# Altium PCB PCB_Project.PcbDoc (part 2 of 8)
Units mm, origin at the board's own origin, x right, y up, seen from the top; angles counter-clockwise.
Board outline 250 x 200 mm, 6 copper layers (Top Shielding/Sig, Sig 1, PWR, GND, Sig 4, Bottom Shielding/Sig), stack 1.568 mm thick; 736 components, 420 nets, 1929 pads, 2185 vias.
Unrouted connection lines stored in the file: 47.
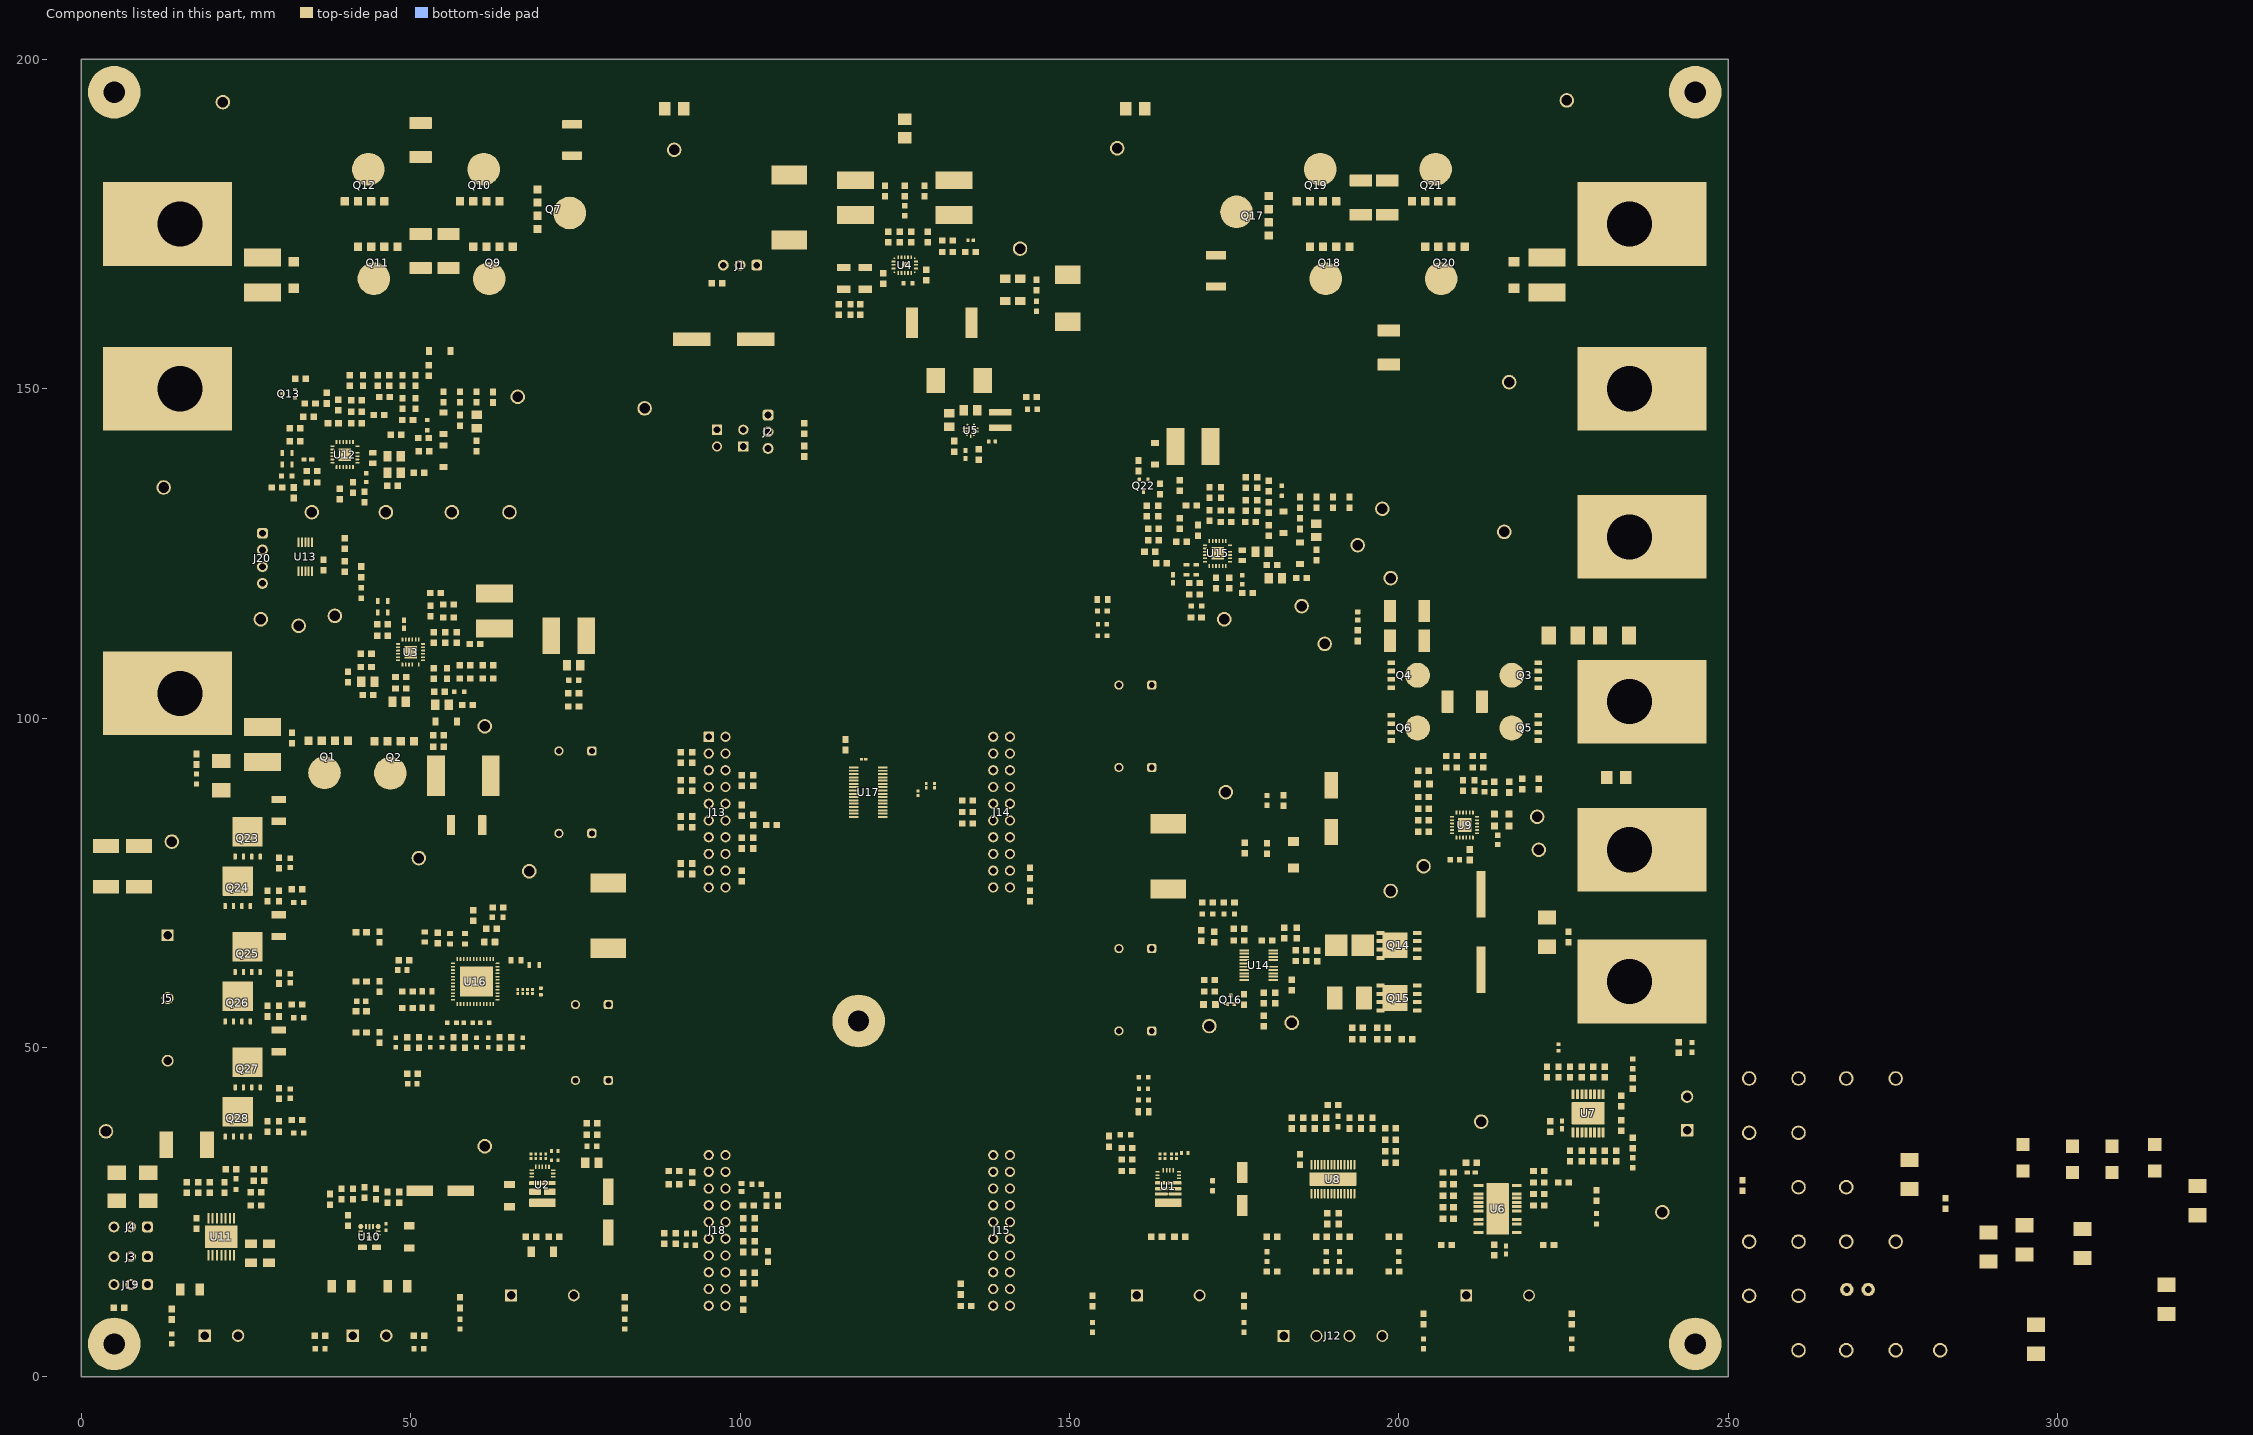
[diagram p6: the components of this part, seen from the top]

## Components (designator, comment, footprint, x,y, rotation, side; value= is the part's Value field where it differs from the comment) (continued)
R215 "RC0603FR-07205RL" 0603 174.25,72 r180 top value=205
R216 "VMP-1R00-1.0-U" FP-VMP-1R00-1.0-U_2010-MFG 172.25,167.875 r90 top value=1
R217 "CRCW06030000Z0EA" 0603 163.75,134.75 r90 top value=0
R218 "CRCW06030000Z0EA" 0603 161.75,131.45 r90 top value=0
R219 "CRCW06030000Z0EA" 0603 180.75,123.25 r0 top value=0
R220 "CSS2H-2512R-L500F" FP-CSS2H-2512R-L500F_2512-MFG 194.25,179 r90 top value=500µ
R221 "RC0805FR-0710RL" 0805_HV 181.25,121.25 r180 top value=10.0
R222 "CSS2H-2512R-L500F" FP-CSS2H-2512R-L500F_2512-MFG 198.25,179 r90 top value=500µ
R223 "HoLRS2512-0.25mR-1%" FP-HoLRS2512_2512-MFG 198.5,156.25 r90 top value=250µ
R224 "CRCW06030000Z0EA" 0603 176.75,135.75 r90 top value=0
R225 "CRCW06030000Z0EA" 0603 178.5,135.75 r90 top value=0
R226 "CRCW06030000Z0EA" 0603 168.5,132.25 r180 top value=0
R227 "ERJ-3EKF1000V" 0603 173,134.25 r90 top value=100
R228 "RC0603FR-07200RL" 0603 176.75,132.25 r90 top value=200
R229 "RC0603FR-07200RL" 0603 178.5,132.25 r90 top value=200
R230 "RC0603FR-072R21L" 0603 187.5,132.75 r90 top value=2.21
R231 "RC0603FR-072R21L" 0603 192.5,132.75 r90 top value=2.21
R232 "RC0603FR-072R21L" 0603 190,132.75 r90 top value=2.21
R233 "RC0603FR-072R21L" 0603 185,132.75 r90 top value=2.21
R234 "RC0805FR-0710RL" 0805_HV 187.5,128.5 r90 top value=10.0
R235 "RC0603FR-07300KL" 0603 167,126.75 r180 top value=300k
R236 "RC0603FR-0775KL" 0603 160.5,138.3 r90 top value=75.0k
R237 "RC0603FR-071KL" 0603 162.75,127 r0 top value=1.00k
R238 "RC0603FR-07698RL" 0603 171.25,134.25 r90 top value=698
R239 "RC0603FR-071KL" 0603 162.75,128.75 r0 top value=1.00k
R240 "CRCW06030000Z0EA" 0603 180.25,131.95 r270 top value=0
R241 "RC0603FR-07309RL" 0603 180.25,135.2 r90 top value=309
R242 "RC0603FR-071KL" 0603 162.2,125.25 r0 top value=1.00k
R243 "CRCW06030000Z0EA" 0603 185,129.5 r270 top value=0
R244 "RC0603FR-07205RL" 0603 169.25,115.25 r180 top value=205
R245 "TNPW060310K0BEEA" TNPW0603 169.25,122.5 r270 top value=10.0k
R246 "RC0603FR-071KL" 0603 144,76.5 r90 top value=1.00k
R247 "TNPW060310K0BEEA" TNPW0603 167.75,122.5 r270 top value=10.0k
R248 "RC0603FR-071KL" 0603 144,73 r90 top value=1.00k
R249 "RC0603FR-072K2L" 0603 92.75,84.25 r90 top value=2.20k
R250 "RC0603FR-0712K1L" 0603 174.25,120.5 r90 top value=12.1k
R251 "CRCW0603100KFKEA" 0603 169,118.75 r0 top value=100k
R252 "RC0603FR-0740K2L" 0603 172.25,120.5 r90 top value=40.2k
R253 "RC0603FR-072K49L" 0603 32.75,74 r180 top value=2.49k
R254 "RC0603FR-072K49L" 0603 32.75,56.5 r180 top value=2.49k
R255 "RC0603FR-072K49L" 0603 32.75,39 r180 top value=2.49k
R256 "RC0201FR-0722RL" 0201 67.75,58.5 r90 top value=22.0
R257 "RC0402JR-0710KL" FP-RC0402JR-0710KL_0402-MFG 69.75,58.5 r270 top value=10k
R258 "RC0201FR-0722RL" 0201 67,58.5 r90 top value=22.0
R259 "RC0201FR-0722RL" 0201 66.25,58.5 r90 top value=22.0
R260 "RC0201FR-0722RL" 0201 68.5,58.5 r90 top value=22.0
R261 "CRCW0603100KFKEA" 0603L 31.75,78 r270 top value=100k
R262 "TNPW060310K0BEEA" TNPW0603 68.75,62.5 r0 top value=10.0k
R263 "KTR03EZPF3R00" 0603 54.125,66.625 r90 top value=3.00
R264 "ERJ-3GEY0R00V" 0603 45.25,66.75 r270 top value=0
R265 "CRCW0603100KFKEA" 0603L 48.75,61.75 r0 top value=100k
R266 "CRCW0603100KFKEA" 0603L 31.75,60.5 r270 top value=100k
R267 "RC0603FR-07205RL" 0603 63.25,71.25 r0 top value=205
R268 "ERJ-3GEY0R00V" 0603 49,63.25 r0 top value=0
R269 "KTR03EZPF3R00" 0603 49.5,58.5 r0 top value=3.00
R270 "CRCW0603100KFKEA" 0603L 42.5,57 r0 top value=100k
R271 "ERJ-3GEY0R00V" 0603 45.25,59.25 r270 top value=0
R272 "ERJ-3GEY0R00V" 0603 42.5,55.5 r0 top value=0
R273 "CRCW0603100KFKEA" 0603L 31.75,43 r270 top value=100k
R274 "KTR03EZPF3R00" 0603 49.5,56 r0 top value=3.00
R275 "ERJ-3GEY0R00V" 0603 45.25,51.5 r270 top value=0
R276 "ERJ-3GEY0R00V" 0603 50.25,46 r0 top value=0
R277 "CRCW0603100KFKEA" 0603L 50.25,44.5 r0 top value=100k
R278 "RC0603FR-07160RL" 0603 91,89.75 r270 top value=160
R279 "RC0603FR-07160RL" 0603 91,77.125 r270 top value=160
R280 "RC0603FR-07160RL" 0603 104.75,83.75 r0 top value=160
R281 "RC0603FR-0710RL" 0603 49.5,50.75 r270 top value=10.0
R282 "RC0603FR-0710RL" 0603 56.5,50.75 r270 top value=10.0
R283 "RC0603FR-0710RL" 0603 63.5,50.75 r270 top value=10.0
R284 "CRE2512-FZ-R005E-3" CRE2512-R5_R9 8.75,77.5 r270 top value=0.005
R285 "CRE2512-FZ-R005E-3" CRE2512-R5_R9 3.75,77.5 r270 top value=0.005
R286 "CRE2512-FZ-R005E-3" CRE2512-R5_R9 16,35.25 r0 top value=0.005
R287 "RC0603FR-0710RL" 0603 51.25,50.75 r270 top value=10.0
R288 "RC0603FR-0710RL" 0603 58.25,50.75 r270 top value=10.0
R289 "RC0603FR-0710RL" 0603 65.25,50.75 r270 top value=10.0
R290 "ERJ-3EKF1002V" 0603 134.5,87.5 r180 top value=10.0k
R291 "ERJ-3EKF1002V" 0603 134.5,84 r180 top value=10.0k
R292 "ERJ-3EKF1002V" 0603 134.5,85.75 r180 top value=10.0k
R293 "RC0201FR-0722RL" 0201 128.25,89.75 r90 top value=22.0
R294 "RC0201FR-0722RL" 0201 129.5,89.75 r90 top value=22.0
R295 "RC0201FR-0722RL" 0201 118.75,93.75 r180 top value=22.0
R296 "RC0201FR-0722RL" 0201 127,88.58 r90 top value=22.0
R297 "RC0603FR-073K16L" 0603 164,123.5 r0 top value=3.16k
R298 "RC0603FR-07102RL" 0603 52.75,152.75 r90 top value=102
R299 "RC0603FR-0733KL" 0603 39.25,134 r90 top value=33.0k
R300 "RC0603FR-0710RL" 0603 180.25,128.45 r90 top value=10.0
R301 "RC0603FR-07102RL" 0603 166.75,135.3 r90 top value=102
R302 "RC0603FR-071KL" 0603 40,126.5 r90 top value=1.00k
R303 "RC0603FR-0715K4L" 0603 40,123 r90 top value=15.4k
R304 "RNCF0603TKY10K0" 0603 5.7,10.5 r180 top value=10.0k
R305 "CRCW06030000Z0EA" 0603 46,148.75 r180 top value=0
R306 "RC0603FR-0710RL" 0603 283,26.3 r90 top value=10.0
R307 "RC0603FR-0710RL" 0603 252.173,29.036 r90 top value=10.0
RNTC_1 "NCU18WB473J6SRB" FP-NCU18WB473J6SRB_0603-MFG 57.375,104 r0 top value=47kΩ
RNTC_2 "NCU18WB473J6SRB" FP-NCU18WB473J6SRB_0603-MFG 52.5,144.475 r90 top value=47kΩ
RNTC_3 "NCU18WB473J6SRB" FP-NCU18WB473J6SRB_0603-MFG 182.25,134.5 r90 top value=47kΩ
S1 "LPM Button" SW_147873-2 7.75,31 r0 top
S2 "RST" SW_147873-2 7.75,26.75 r180 top
SH-J1 "SNT-100-BK-G" SNT-100-BK-G 100,168.75 r180 top value=1x2
SH-J2 "SNT-100-BK-G" SNT-100-BK-G 104.75,142.5 r90 top value=1x2
SH-J3 "SNT-100-BK-G" SNT-100-BK-G 96.5,142.5 r90 top value=1x2
SH-J4 "SNT-100-BK-G" SNT-100-BK-G 100.5,142.5 r90 top value=1x2
T1 "JUMP_START" Panduit_CXS70-14-C 235,80 r180 top locked
T2 "12V_OFF_BOARD_DCDC" Panduit_CXS70-14-C 235,102.5 r180 top locked
T3 "48V_OFF_BOARD_DCDC" Panduit_CXS70-14-C 235,127.5 r180 top locked
T4 "48V_BAT_IN1" Panduit_CXS70-14-C 15,175 r0 top locked
T5 "GND" Panduit_CXS70-14-C 15,150 r0 top locked
T6 "48V_BAT_IN2" Panduit_CXS70-14-C 235,175 r180 top
T7 "GND" Panduit_CXS70-14-C 235,150 r180 top locked
T8 "VOUT_TPS1214" Panduit_CXS70-14-C 15,103.75 r0 top locked
T9 "VOUT_TPS1211" Panduit_CXS70-14-C 235,60 r180 top locked
TP1 "12V_DRV8245" Keystone5010 171.25,53.25 r180 top
TP2 "48V" Keystone5010 51.25,78.75 r180 top
TP3 "48V_DRV8263" Keystone5010 61.25,35 r90 top
TP4 "G_TPS1214" Keystone5012 27.25,115 r180 top
TP5 "GATE_TPS1214" Keystone5012 61.25,98.75 r180 top
TP6 "I2t_TPS1214" Keystone5012 33,114 r0 top
TP7 "IMON_TPS1214" Keystone5012 38.5,115.5 r0 top
TP8 "COBRA_VOUT" Keystone5010 142.5,171.25 r180 top
TP9 "12V_IN" Keystone5010 221.25,80 r90 top
TP10 "12V" Keystone5010 198.75,121.25 r90 top
TP11 "HGATE_LM74900" Keystone5012 188.75,111.25 r0 top
TP12 "DGATE_LM74900" Keystone5012 221,85 r90 top
TP13 "G_TPS1212_input1" Keystone5012 56.25,131.25 r90 top
TP14 "48V" Keystone5010 85.5,147 r90 top
TP15 "48V_BAT_IN1" Keystone5010 21.5,193.5 r90 top
TP16 "GATE_TPS1212_input1" Keystone5012 66.25,148.75 r0 top
TP17 "I2t_TPS1212_input1" Keystone5012 46.25,131.25 r90 top
TP18 "IMON_TPS1212_input1" Keystone5012 35,131.25 r0 top
TP19 "G_TPS1211" Keystone5012 183.75,53.75 r90 top
TP20 "TPS1211_VS" Keystone5010 212.5,38.75 r180 top
TP21 "GATE_TPS1211" Keystone5012 198.75,73.75 r0 top
TP22 "IMON_TPS1211" Keystone5012 173.75,88.75 r0 top
TP23 "G_TPS1212_input2" Keystone5012 185.25,117 r90 top
TP24 "48V" Keystone5010 216,128.25 r90 top
TP25 "48V_BAT_IN2" Keystone5010 225.5,193.75 r90 top
TP26 "GATE_TPS1212_input2" Keystone5012 197.5,131.75 r90 top
TP27 "I2t_TPS1212_input2" Keystone5012 193.75,126.25 r0 top
TP28 "IMON_TPS1212_input2" Keystone5012 173.5,115 r0 top
TP29 "GND" Keystone5011 65,131.25 r0 top
TP30 "GND" Keystone5011 13.75,81.25 r180 top
TP31 "GND" Keystone5011 12.5,135 r180 top
TP32 "GND" Keystone5011 157.25,186.5 r0 top
TP33 "GND" Keystone5011 68,76.75 r0 top
TP34 "GND" Keystone5011 90,186.25 r0 top
TP35 "GND" Keystone5011 203.75,77.5 r90 top
TP36 "GND" Keystone5011 240,25 r0 top
TP37 "GND" Keystone5011 3.75,37.25 r90 top
TP38 "GND" Keystone5011 216.75,151 r0 top
TP39 "VS+" Keystone5012 275.423,45.286 r0 top
TP40 "VS-" Keystone5012 267.923,45.286 r0 top
TP41 "VDD+" Keystone5012 275.423,4.036 r0 top
TP42 "VDD-" Keystone5012 282.173,4.036 r0 top
TP43 "VBB+" Keystone5012 260.673,4.036 r0 top
TP44 "VBB-" Keystone5012 267.923,4.036 r0 top
TP45 "VBB+" Keystone5012 260.673,28.786 r0 top
TP46 "VBB-" Keystone5012 267.923,28.786 r0 top
TP47 "5002" Keystone5002 271.25,13.25 r90 top
TP48 "5002" Keystone5002 268,13.25 r90 top
TP49 "VS+" Keystone5012 275.423,20.536 r0 top
TP50 "VS-" Keystone5012 267.923,20.536 r0 top
TP51 "1212_1_SRC" Keystone5012 260.673,12.286 r0 top
TP52 "1212_1_BST" Keystone5012 253.173,12.286 r0 top
TP53 "1212_2_SRC" Keystone5012 260.673,20.536 r0 top
TP54 "1212_2_BST" Keystone5012 253.173,20.536 r0 top
TP55 "1214_SRC" Keystone5012 260.673,45.286 r0 top
TP56 "1214_BST" Keystone5012 253.173,45.286 r0 top
TP57 "1211_SRC" Keystone5012 260.673,37.036 r0 top
TP58 "1211_BST" Keystone5012 253.173,37.036 r0 top
U1 "DRV8245SQRXZRQ1" RXZ0016A-MFG 165,28.75 r0 top
U2 "DRV8263SQVAKRQ1" VAK0015A-MFG 70,29 r0 top locked
U3 "TPS12140-Q1" RGE0023A-MFG#1 50,110 r270 top
U4 "LM68645SCRZTRQ1" RZT0020A-MFG 125,168.75 r270 top locked
U5 "TPS62903QRYTQ1" RYT0009A-MFG 135,143.75 r180 top locked
U6 "TPS2HCS05A" PWC0018A-MFG 215,25.5 r0 top locked
U7 "TPS2HCS10-Q1" PWP0016P-MFG 228.75,40 r90 top
U8 "TPS4HC120-Q1" DGQ0028A-MFG 190,30 r270 top locked
U9 "LM74900QRGERQ1" RGE0024T-MFG 210,83.75 r180 top locked
U10 "TPS482H85BQCHURQ1" CHU0012A-MFG 43.75,21.25 r90 top locked
U11 "TPS1HTC30AQPWPRQ1" PWP0014C-MFG 21.25,21.25 r270 top locked
U12 "TPS12120-Q1" RGE0023A-MFG#2 40,140 r0 top
U13 "TPLD1201DGS" DGS0010A-MFG 34,124.5 r270 top
U14 "TPS12111LQDGXRQ1" DGX0019A-MFG 178.75,62.5 r0 top locked
U15 "TPS12120-Q1" RGE0023A-MFG#2 172.5,125 r0 top
U16 "DRV8363RGZRQ1" RGZ0048L-MFG 59.812,60 r90 top locked
U17 "TXE8124QDGSRQ1" DGS0032A-MFG 119.45,88.75 r0 top
ZZ1 "This Assembly Note is for PCB labels only" AssemblyNoteLabel 201,-3 r0 top
ZZ2 "These assemblies are ESD sensitive, ESD precautions shall be observed." AssemblyNote 201,-5 r0 top
ZZ3 "These assemblies must be clean and free from flux and all contaminants. Use of no clean flux is not acceptable." AssemblyNote 201,-7 r0 top
ZZ4 "These assemblies must comply with workmanship standards IPC-A-610 Class 2, unless otherwise specified." AssemblyNote 201,-9 r0 top

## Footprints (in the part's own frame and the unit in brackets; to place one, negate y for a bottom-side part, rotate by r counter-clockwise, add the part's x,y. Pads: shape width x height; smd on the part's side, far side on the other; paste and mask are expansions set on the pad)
0201 [mm] "Data from Kemet datasheet CC101_COM dated 7/28/11"
  rect 0.46x0.42 smd mask+0.048: 1(-0.33,0) 2(0.33,0)
  body extent -0.31,-0.16 0.31,0.16, height 0.26
0402 [mm] "0402 from SM-752 data"
  rect 0.8x0.6 smd: 1(-0.6,0) 2(0.6,0)
  silkscreen extent -1.22,-0.52 1.22,0.52, body extent -0.55,-0.3 0.55,0.3, height 0.6
0603 [mm] "0603 from SM-752 data"
  rect 1x0.95 smd: 1(-0.8,0) 2(0.8,0)
  silkscreen extent -1.52,-0.69 1.52,0.69, body extent -0.87,-0.47 0.87,0.47, height 1
0603L [mm] "0603 from SM-752 data"
  rect 0.8x0.85 smd: 1(-0.7,0) 2(0.7,0)
  silkscreen extent -0.07,-0.33 0.07,0.32, body extent -0.87,-0.47 0.87,0.47, height 1
0805_HV [mil] "0805 with 30mil clearance between pads"
  rect 50x63 smd: 1(-40,0) 2(40,0)
  silkscreen extent -74,-40 74,40, body extent -43,-29 43,29, height 57
1206 [mm] "1206 from SM-752 data"
  rect 1.3x1.85 smd: 1(-1.45,0) 2(1.45,0)
  silkscreen extent -2.4,-1.21 2.4,1.21, body extent -1.7,-0.9 1.7,0.9, height 1.35
1206_180 [mm] "1206_180"
  rect 1.1x1.6 smd: 1(-1.7,0) 2(1.7,0)
  silkscreen extent -0.9,-1 0.9,1, body extent -1.75,-0.95 1.75,0.95, height 1.8
1210_280 [mm] "SMD, 2-Leads, Body 3.6x2.8mm, Height 2.8mm"
  rect 1.1x2.2 smd: 1(-1.65,0) 2(1.65,0)
  silkscreen extent -0.84,-1.4 0.84,1.4, body extent -1.8,-1.4 1.8,1.4, height 2.8
AFK_1250x1350 [mm] "SMD, 2-Leads, Dia 12.5mm"
  rect 7.05x1.35 smd: 1(-5.725,0) 2(5.725,0)
  silkscreen extent -6.75,-6.75 6.75,6.75, body extent -7.5,-6.75 7.5,6.75, height 14
AssemblyNote [mm] "Assembly Note"
AssemblyNoteLabel [mm] "Assembly Note for PCB Labels"
BoosterPack_40pin_J1J3 [mm] "Receptacle, 2.54mm, 10x2, TH"
  rrect6% 1.55x1.55 hole 1.02: 1(1.27,11.43)
  round 1.55 hole 1.02: 2(1.27,8.89) 3(1.27,6.35) 4(1.27,3.81) 5(1.27,1.27) 6(1.27,-1.27) 7(1.27,-3.81) 8(1.27,-6.35) 9(1.27,-8.89) 10(1.27,-11.43) 21(-1.27,11.43) 22(-1.27,8.89) 23(-1.27,6.35) 24(-1.27,3.81) 25(-1.27,1.27) 26(-1.27,-1.27) 27(-1.27,-3.81) 28(-1.27,-6.35) 29(-1.27,-8.89) 30(-1.27,-11.43)
  silkscreen extent -7.62,-12.95 7.62,12.95, body extent -2.48,-12.95 2.48,12.95, height 8.51
BoosterPack_40pin_J2J4 [mm] "Receptacle, 2.54mm, 10x2, TH"
  round 1.55 hole 1.02: 11(-1.27,-11.43) 12(-1.27,-8.89) 13(-1.27,-6.35) 14(-1.27,-3.81) 15(-1.27,-1.27) 16(-1.27,1.27) 17(-1.27,3.81) 18(-1.27,6.35) 19(-1.27,8.89) 20(-1.27,11.43) 31(1.27,-11.43) 32(1.27,-8.89) 33(1.27,-6.35) 34(1.27,-3.81) 35(1.27,-1.27) 36(1.27,1.27) 37(1.27,3.81) 38(1.27,6.35) 39(1.27,8.89) 40(1.27,11.43)
  silkscreen extent -7.62,-12.95 2.48,12.95, body extent -2.48,-12.95 2.48,12.95, height 8.51
BoosterPack_40pin_J5J7 [mm] "Receptacle, 2.54mm, 10x2, TH"
  round 1.55 hole 1.02: 41(1.27,11.43) 42(1.27,8.89) 43(1.27,6.35) 44(1.27,3.81) 45(1.27,1.27) 46(1.27,-1.27) 47(1.27,-3.81) 48(1.27,-6.35) 49(1.27,-8.89) 50(1.27,-11.43) 61(-1.27,11.43) 62(-1.27,8.89) 63(-1.27,6.35) 64(-1.27,3.81) 65(-1.27,1.27) 66(-1.27,-1.27) 67(-1.27,-3.81) 68(-1.27,-6.35) 69(-1.27,-8.89) 70(-1.27,-11.43)
  silkscreen extent -7.62,-12.95 7.62,12.95, body extent -2.48,-12.95 2.48,12.95, height 8.51
BoosterPack_40pin_J6J8 [mm] "Receptacle, 2.54mm, 10x2, TH"
  round 1.55 hole 1.02: 51(-1.27,-11.43) 52(-1.27,-8.89) 53(-1.27,-6.35) 54(-1.27,-3.81) 55(-1.27,-1.27) 56(-1.27,1.27) 57(-1.27,3.81) 58(-1.27,6.35) 59(-1.27,8.89) 60(-1.27,11.43) 71(1.27,-11.43) 72(1.27,-8.89) 73(1.27,-6.35) 74(1.27,-3.81) 75(1.27,-1.27) 76(1.27,1.27) 77(1.27,3.81) 78(1.27,6.35) 79(1.27,8.89) 80(1.27,11.43)
  silkscreen extent -7.62,-12.95 2.48,12.95, body extent -2.48,-12.95 2.48,12.95, height 8.51
CE_Mark_5mm [mm] "Minimum text height for CE Mark"
  silkscreen extent -3.5,-2.5 3.5,2.5
CHU0012A-MFG [mm]
  rrect25% 0.8x1.4 smd paste-1000 mask-1000: 1(-1.6,1.05) 2(-1.6,-1.05)
  round 0.691 smd paste-1000 mask+0: 3(-0.162,0.042)
  rrect40% 0.25x0.7 smd paste+0 mask+0: 4(0.325,-1.35) 5(0.825,-1.35) 11(0.825,1.35) 12(0.325,1.35)
  round 0.764 smd paste-1000 mask-1000: 6(1.575,-1.325) 10(1.575,1.326)
  rrect33% 0.75x0.3 smd paste+0 mask+0: 7(1.575,-0.55) 9(1.575,0.55)
  rrect33% 0.8x0.3 smd paste+0 mask+0: 8(1.55,0)
  Top Shielding/Sig region: 1.25,-1.75 1.212,-1.742 1.179,-1.721 1.158,-1.688 1.15,-1.65 1.15,-1.65 1.15,-1.116 1.166,-1.034 1.213,-0.964 1.283,-0.917 1.365,-0.901 1.365,-0.901 1.9,-0.901 1.95,-0.914 1.987,-0.951 2,-1.001 2,-1.001 2,-1.65 1.987,-1.7 1.95,-1.737 1.9,-1.75 1.9,-1.75
  Top Shielding/Sig region: 1.25,1.75 1.212,1.742 1.179,1.721 1.158,1.688 1.15,1.65 1.15,1.65 1.15,1.116 1.166,1.034 1.213,0.964 1.283,0.917 1.365,0.901 1.365,0.901 1.9,0.901 1.938,0.909 1.971,0.93 1.992,0.963 2,1.001 2,1.001 2,1.65 1.992,1.688 1.971,1.721 1.938,1.742 1.9,1.75 1.9,1.75
  Top Shielding/Sig region: -0.65,1.65 -0.643,1.675 -0.625,1.693 -0.6,1.7 -0.6,1.7 -0.45,1.7 -0.431,1.696 -0.415,1.685 -0.404,1.669 -0.4,1.65 -0.4,1.65 -0.4,0.863 -0.392,0.825 -0.371,0.793 -0.371,0.793 0.093,0.329 0.125,0.308 0.163,0.3 0.163,0.3 0.415,0.3 0.44,0.293 0.458,0.275 0.465,0.25 0.465,0.25 0.465,-0.25 0.458,-0.275 0.44,-0.293 0.415,-0.3 0.415,-0.3 0.163,-0.3 0.125,-0.308 0.093,-0.329 0.093,-0.329 -0.371,-0.8 -0.392,-0.832 -0.4,-0.87 -0.4,-0.87 -0.4,-1.65 -0.404,-1.669 -0.415,-1.685 -0.431,-1.696 -0.45,-1.7 -0.45,-1.7 -0.6,-1.7 -0.625,-1.693 -0.643,-1.675 -0.65,-1.65 -0.65,-1.65
  silkscreen extent -2.62,-1.92 2.18,1.93, body extent -2.1,-1.85 2.1,1.85, height 0.25
CRE2512-R5_R9 [mm] "SMD, 2-Leads, Body 6.45x3.35mm, Pitch 6.2mm"
  rect 2.1x4 smd: 1(-3.1,0) 2(3.1,0)
  silkscreen extent -1.6,-1.78 1.6,1.78, body extent -3.32,-1.77 3.32,1.77, height 0.9
DGQ0028A-MFG [mm]
  rrect33% 1.4x0.3 smd paste+0 mask+0: 1(-2.2,3.25) 2(-2.2,2.75) 3(-2.2,2.25) 4(-2.2,1.75) 5(-2.2,1.25) 6(-2.2,0.75) 7(-2.2,0.25) 8(-2.2,-0.25) 9(-2.2,-0.75) 10(-2.2,-1.25) 11(-2.2,-1.75) 12(-2.2,-2.25) 13(-2.2,-2.75) 14(-2.2,-3.25) 15(2.2,-3.25) 16(2.2,-2.75) 17(2.2,-2.25) 18(2.2,-1.75) 19(2.2,-1.25) 20(2.2,-0.75) 21(2.2,-0.25) 22(2.2,0.25) 23(2.2,0.75) 24(2.2,1.25) 25(2.2,1.75) 26(2.2,2.25) 27(2.2,2.75) 28(2.2,3.25)
  rrect5% 2x7.1 smd paste-1000 mask-1000: 29(0,0)
  silkscreen extent -3.57,-3.93 1.55,3.93, body extent -2.46,-3.55 2.46,3.55, height 1.1
DGS0010A-MFG [mm]
  rrect33% 1.45x0.3 smd paste+0 mask+0: 1(-2.2,1) 2(-2.2,0.5) 3(-2.2,0) 4(-2.2,-0.5) 5(-2.2,-1) 6(2.2,-1) 7(2.2,-0.5) 8(2.2,0) 9(2.2,0.5) 10(2.2,1)
  silkscreen extent -3.6,-1.55 1.05,1.55, body extent -3.03,-1.8 3.03,1.8, height 0.25
DGS0032A-MFG [mm]
  rrect33% 1.45x0.3 smd paste+0 mask+0: 1(-2.2,3.75) 2(-2.2,3.25) 3(-2.2,2.75) 4(-2.2,2.25) 5(-2.2,1.75) 6(-2.2,1.25) 7(-2.2,0.75) 8(-2.2,0.25) 9(-2.2,-0.25) 10(-2.2,-0.75) 11(-2.2,-1.25) 12(-2.2,-1.75) 13(-2.2,-2.25) 14(-2.2,-2.75) 15(-2.2,-3.25) 16(-2.2,-3.75) 17(2.2,-3.75) 18(2.2,-3.25) 19(2.2,-2.75) 20(2.2,-2.25) 21(2.2,-1.75) 22(2.2,-1.25) 23(2.2,-0.75) 24(2.2,-0.25) 25(2.2,0.25) 26(2.2,0.75) 27(2.2,1.25) 28(2.2,1.75) 29(2.2,2.25) 30(2.2,2.75) 31(2.2,3.25) 32(2.2,3.75)
  silkscreen extent -2.32,-4.1 1,4.57, body extent -3.03,-4.35 3.03,4.35, height 0.25
DGX0019A-MFG [mm] "Recommended Land Pattern"
  rrect33% 1.45x0.3 smd paste+0 mask+0: 1(-2.2,2.25) 2(-2.2,1.75) 3(-2.2,1.25) 4(-2.2,0.75) 5(-2.2,0.25) 6(-2.2,-0.25) 7(-2.2,-0.75) 8(-2.2,-1.25) 9(-2.2,-1.75) 10(-2.2,-2.25) 11(2.2,-2.25) 12(2.2,-1.75) 13(2.2,-1.25) 14(2.2,-0.75) 15(2.2,-0.25) 17(2.2,0.75) 18(2.2,1.25) 19(2.2,1.75) 20(2.2,2.25)
  silkscreen extent -3.6,-2.6 1.1,2.6, body extent -3.03,-2.85 3.03,2.85, height 0.25
Diode_1408 [mm] "On Semi recommended land pattern for SOD-123"
  rect 1.75x2 smd: 1(-1.425,0) 2(1.425,0)
  silkscreen extent -2.97,-1.35 2.26,1.35, body extent -1.8,-1.05 1.8,1.05, height 1.35
DQJ0008A [mm] "SMD, 8-Leads, Body 5.75x4.9mm"
  rrect39% 0.91x0.51 smd paste-0.05 mask-0.05: 1(-2.795,1.905) 2(-2.795,0.635) 3(-2.795,-0.635) 4(-2.795,-1.905) 5(2.795,-1.905) 6(2.795,-0.635) 7(2.795,0.635) 8(2.795,1.905)
  rrect8% 1.58x1.25 on Top Paste: 9(-0.38,1.45) 9(-0.38,0) 9(-0.38,-1.45) 9(1.4,-1.45) 9(1.4,0) 9(1.4,1.45)
  rrect3% 3.48x4.47 on Top Solder: 9(0.55,0)
  rrect2% 4.49x4.57 smd paste-2.5 mask-2.5: 9(1.005,0)
  silkscreen extent -3,-2.6 3,2.6, body extent -3.13,-2.45 3.13,2.45, height 1.15
FCC_disclaimer [mm]
Foxconn_HB3902U [mm] "Header, 2.54mm, 2x1, TH"
  rrect6% 1.55x1.55 hole 1.02: 1(-1.27,0)
  round 1.55 hole 1.02: 2(1.27,0)
  silkscreen extent -2.42,-1.7 2.41,1.23, body extent -2.41,-1.23 2.42,1.24, height 8.38
FP-06035C104J4Z2A_0603-MFG [mm]
  rrect13% 0.8x0.75 smd paste+0 mask+0: 1(-0.75,0) 2(0.75,0)
  silkscreen extent -0.87,-0.77 0.87,0.77, body extent -1.25,-0.58 1.25,0.58, height 0.25
FP-885012206120_0603-MFG [mm]
  rrect13% 0.8x0.8 smd paste+0 mask+0: 1(-0.75,0) 2(0.75,0)
  silkscreen extent -0.85,-0.78 0.85,0.77, body extent -1.25,-0.55 1.25,0.55, height 0.25
FP-AGC0603X7R250-105KXP_0603-MFG [mm] "Recommended Land Pattern"
  rrect10% 1x1 smd paste+0 mask+0: 1(-0.8,0) 2(0.8,0)
  silkscreen extent -0.87,-0.87 0.87,0.87, body extent -1.4,-0.6 1.4,0.6, height 0.25
FP-ALN2512F50R0E-1_2512-MFG [mm]
  rrect3% 3.4x3.3 smd paste+0 mask+0: 1(-2.005,0) 2(2.005,0)
  silkscreen extent -3.25,-2.09 3.24,2.07, body extent -3.8,-1.75 3.8,1.75, height 0.25
FP-BUK7J1R4-40HX_LFPAK56E-MFG [mm]
  rrect14% 0.7x1.15 smd paste-1000 mask+0: 1(-1.905,-3.137) 2(-0.635,-3.137) 3(0.635,-3.137) 4(1.905,-3.137)
  round 3.78 smd paste-1000 mask+0: 5(0,0.845)
  Top Shielding/Sig region: -2.35,3.087 2.35,3.087 2.35,1.588 2.1,1.588 2.1,-1.512 -2.1,-1.512 -2.1,1.587 -2.35,1.587
  silkscreen extent -2.65,-4.43 2.65,-1.89, body extent -2.9,-3.81 2.9,3.19, height 0.25
FP-C0402C100K5RAC7867_0402-MFG [mm]
  rrect19% 0.52x0.52 smd paste+0 mask+0: 1(-0.4,0) 2(0.4,0)
  silkscreen extent -0.5,-0.63 0.5,0.64, body extent -0.8,-0.4 0.8,0.4, height 0.25
FP-C0603C104J5RAC7867_0603-MFG [mm]
  rrect13% 0.75x0.9 smd paste+0 mask+0: 1(-0.6,0) 2(0.6,0)
  silkscreen extent -0.87,-0.83 0.88,0.82, body extent -1.2,-0.6 1.2,0.6, height 0.25
FP-CGA3E2X7R1H102K080AA_0603-MFG [mm]
  rrect14% 0.7x0.7 smd paste+0 mask+0: 1(-0.7,0) 2(0.7,0)
  silkscreen extent -0.95,-0.72 0.95,0.72, body extent -1.15,-0.65 1.15,0.65, height 0.25
FP-CL10B104KA8VPJC_0603-MFG [mm]
  rrect13% 0.79x1 smd paste+0 mask+0: 1(-0.755,0) 2(0.755,0)
  silkscreen extent -0.9,-0.87 0.9,0.87, body extent -1.25,-0.6 1.25,0.6, height 0.25
FP-CL10B105KA8VPJC_0603-MFG [mm]
  rrect13% 0.79x1 smd paste+0 mask+0: 1(-0.755,0) 2(0.755,0)
  silkscreen extent -0.9,-0.87 0.9,0.87, body extent -1.25,-0.6 1.25,0.6, height 0.25
FP-CL10B105KB9VPJC_0603-MFG [mm]
  rrect12% 0.82x1.1 smd paste+0 mask+0: 1(-0.79,0) 2(0.79,0)
  silkscreen extent 0,-0.5 0,0.5, body extent -1.3,-0.65 1.3,0.65, height 0.25
FP-CL10B562KB8NNNC_0603-IPC_C [mm]
  rrect13% 0.758x0.812 smd paste+0 mask+0: 1(-0.627,0) 2(0.627,0)
  silkscreen extent -1.01,-0.85 1.01,0.85, body extent -1.11,-0.55 1.11,0.55, height 0.25
FP-CSS2H-2512R-L500F_2512-MFG [mm]
  rrect6% 1.8x3.4 smd paste+0 mask+0: 1(-2.6,0) 2(2.6,0)
  silkscreen extent -1.33,-1.63 1.33,1.63, body extent -3.6,-1.8 3.6,1.8, height 0.25
FP-EEE-HA1H100P_RADIAL-MFG [mm]
  rrect6% 3.2x1.6 smd paste+0 mask+0: 1(-2.5,0) 2(2.5,0)
  silkscreen extent -4.77,-3.4 3.4,3.4, body extent -4.35,-3.65 4.35,3.65, height 0.25
FP-EMK316BB7226ML-T_1206-MFG [mm] "Recommended Land Pattern"
  rrect8% 1.25x1.6 smd paste+0 mask+0: 1(-1.7,0) 2(1.7,0)
  silkscreen extent -0.7,-0.95 0.7,0.95, body extent -2.42,-1.05 2.42,1.05, height 0.25
FP-ERJ-PB3B1003V_0603-IPC_A [mm]
  rrect9% 1.057x1.062 smd paste+0 mask+0: 1(-0.901,0) 2(0.901,0)
  silkscreen extent -1.43,-0.93 1.43,0.93, body extent -1.93,-1.03 1.93,1.03, height 0.25
FP-GCE188R71H103KA01D_0603-MFG [mm]
  rrect15% 0.65x0.7 smd paste+0 mask+0: 1(-0.675,0) 2(0.675,0)
  silkscreen extent -1,-0.72 1,0.72, body extent -1.1,-0.55 1.1,0.55, height 0.25
FP-GCJ32DC72A475KE01L_1210-MFG [mm]
  rrect9% 1.1x2.05 smd paste+0 mask+0: 1(-1.65,0) 2(1.65,0)
  silkscreen extent -1.8,-1.4 1.8,1.4, body extent -2.3,-1.5 2.3,1.5, height 0.25
FP-GCJ188R71E104KA12D_0603-MFG [mm]
  rrect15% 0.65x0.7 smd paste+0 mask+0: 1(-0.675,0) 2(0.675,0)
  silkscreen extent -0.9,-0.79 0.9,0.78, body extent -1.1,-0.55 1.1,0.55, height 0.25
FP-GRM188D72A105KE01D_0603-MFG [mm] "Recommended Land Pattern"
  rrect13% 0.75x0.9 smd paste+0 mask+0: 1(-0.775,0) 2(0.775,0)
  silkscreen extent -0.9,-0.9 0.9,0.9, body extent -0.8,-0.4 0.8,0.4, height 1
FP-HoLRS2512_2512-MFG [mm] "Recommended Land Pattern"
  rrect6% 1.8x3.4 smd paste+0 mask+0: 1(-2.6,0) 2(2.6,0)
  silkscreen extent -1.33,-1.75 1.33,1.75, body extent -3.6,-1.85 3.6,1.85, height 0.25
FP-NCU18WB473J6SRB_0603-MFG [mm]
  rrect15% 0.65x0.7 smd paste+0 mask+0: 1(-0.775,0) 2(0.775,0)
  silkscreen extent -0.88,-0.72 0.87,0.72, body extent -1.2,-0.58 1.2,0.58, height 0.25
FP-NVMTS1D2N08H_DFNW8-MFG [mm]
  rrect8% 1.25x1.28 smd paste+0 mask+0: 1(-3,-4.07) 2(-1,-4.07) 3(1,-4.07) 4(3,-4.07)
  round 4.956 smd paste+0 mask+0: 5-6-7-8(0.583,0.814)
  Top Shielding/Sig region: -3.625,4.71 -2.375,4.71 -2.375,3.56 -1.625,3.56 -1.625,4.71 -0.375,4.71 -0.375,3.56 0.375,3.56 0.375,4.71 1.625,4.71 1.625,3.56 2.375,3.56 2.375,4.71 3.625,4.71 3.625,3.38 3.5,3.38 3.5,-1.94 -3.5,-1.94 -3.5,3.38 -3.625,3.38
  Keep-Out Layer region: -4.05,-1.94 4.05,-1.94 4.05,3.56 -4.05,3.56
  silkscreen extent -4.05,-5.4 4.05,4, body extent -4.15,-4.2 4.15,4.2, height 1.2
FP-RC0402JR-0710KL_0402-MFG [mm]
  rrect20% 0.5x0.6 smd paste+0 mask+0: 1(-0.5,0) 2(0.5,0)
  silkscreen extent -0.5,-0.67 0.5,0.68, body extent -0.85,-0.4 0.85,0.4, height 0.25
FP-ULRG32512R001FLFSLT_2512-MFG [mm]
  rrect4% 2.38x3.45 smd paste+0 mask+0: 1(-2.21,0) 2(2.21,0)
  silkscreen extent -0.64,-1.6 0.64,1.6, body extent -3.5,-1.83 3.5,1.83, height 0.25
FP-VMP-1R00-1.0-U_2010-MFG [mm]
  rrect8% 1.25x3 smd paste+0 mask+0: 1(-2.375,0) 2(2.375,0)
  silkscreen extent -1.38,-1.37 1.37,1.37, body extent -3.1,-1.6 3.1,1.6, height 0.25
FP-WSL3921L5000FEA_3921-MFG [mm]
  rrect4% 2.7x6.2 smd paste+0 mask+0: 1(-4.15,0) 2(4.15,0)
  silkscreen extent -2.42,-2.79 2.43,2.79, body extent -5.6,-3.2 5.6,3.2, height 0.25
FP-XGL4030-102MEC_SMD_IND_4MM0_4MM0-MFG [mm]
  rrect10% 0.98x3.4 smd paste+0 mask+0: 1(-1.185,0) 2(1.185,0)
  silkscreen extent -2.15,-2.15 2.15,2.15, body extent -2.25,-2.25 2.25,2.25, height 0.25
IEC_HotSurface_Small [mm]
  silkscreen extent -2.72,-2.36 2.72,2.35
KCM55W [mm] "MuRata"
  rect 2.7x5.6 smd: 1(-2.65,0) 2(2.65,0)
  silkscreen extent -1.05,-2.8 1,2.8, body extent -3.25,-2.75 3.25,2.75, height 6.7
Keystone5002 [mil] "For Keystone 500x miniature loop terminals"
  round 80 hole 40: 1(0,0)
  silkscreen extent -52,-52 52,52, body extent -49,-49 49,49, height 182
Keystone5010 [mil] "Keystone Multipurpose loops"
  round 87 hole 63: 1(0,0)
  silkscreen extent -70,-70 70,70, body extent -63,-63 63,62, height 319
Keystone5011 [mil] "Keystone Multipurpose loops"
  round 87 hole 63: 1(0,0)
  silkscreen extent -70,-70 70,70, body extent -63,-63 63,62, height 319
Keystone5012 [mil] "Keystone Multipurpose loops"
  round 87 hole 63: 1(0,0)
  silkscreen extent -70,-70 70,70, body extent -63,-63 63,62, height 319
Keystone_1902C [mil] "Hex Standoff, 4-40 threaded, nylon"
  round 1 on Mech4: 0(0,0)
  body extent -145,-126 146,126, height 501
Label_650x200 [mil] "Thermal Transfer Label"
  round 1 on Mech13: 0(0,0)
  silkscreen extent -325,-100 325,100, body extent -325,-100 325,100, height 1
LTST-C191_Green [mm] "Lite-On"
  rect 0.8x0.8 smd: 1(-0.75,0) 2(0.75,0)
  silkscreen extent -1.1,-0.8 1.8,0.8, body extent -0.85,-0.45 0.85,0.45, height 0.65
"NY PMS 440 0025 PH" [mm] "4-40 nylon screw and mounting hole"
  round 8 hole 3.2: 1(0,0)
  body extent -3.3,-3.3 3.3,3.3, height 2.69
Panasonic_SMT_800x1020 [mm] "SMD, 2-Leads, Dia 8mm"
  rect 4x2 smd: 1(-3.55,0) 2(3.55,0)
  silkscreen extent -4.25,-4.25 4.25,4.25, body extent -4.25,-4.25 4.25,4.25, height 10.51
Panduit_CXS70-14-C [mil] "Panduit"
  rect 770x500 hole 270 copper offset -74.8,0 paste-99999: 1(0,0)
  body extent -960,-250 310,250, height 684
Phoenix_1715048 [mm] "Terminal Block, 5mm, 4x1, TH"
  rect 1.8x1.8 hole 1.3: 1(-7.5,-0.3)
  round 1.8 hole 1.3: 2(-2.5,-0.3) 3(2.5,-0.3) 4(7.5,-0.3)
  silkscreen extent -10.74,-4.9 10,4.9, body extent -10.74,-4.9 10,4.9, height 14.3
Phoenix_1902547 [mm] "TH, 2-Leads, Body 19.04x16mm, Pitch 9.52mm"
  rect 1.8x1.8 hole 1.3: 1(-4.76,3.1)
  round 1.8 hole 1.3: 2(4.76,3.1)
  silkscreen extent -10,-8 10.09,8, body extent -9.52,-8 10.09,8, height 22
Phoenix_1904150 [mm] "TH, 3-Leads, Body 28.56x16mm, Pitch 9.52mm"
  rect 1.8x1.8 hole 1.3: 1(-9.52,3.1)
  round 1.8 hole 1.3: 2(0,3.1) 3(9.52,3.1)
  silkscreen extent -14.8,-8 14.85,8, body extent -14.28,-8 14.85,8, height 22
PhoenixContact_1715721 [mm] "Phoenix Contact 1715721 used on LM3445 design from Longmont"
  rrect5% 1.905x1.905 hole 1.3: 1(-2.54,0)
  round 1.9 hole 1.3: 2(2.54,0)
  silkscreen extent -5.82,-5.25 5.08,5.2, body extent -5.82,-4.6 5.08,5.2, height 14.2
PowerPAK_SO-8 [mil] "Vishay PowerPAK SO-8, Body 5.3x6.0mm (max), Pitch 1.27mm, IPC Medium Density"
  rect 50x24 smd mask+2.99: 1(-109.5,75) 2(-109.5,25) 3(-109.5,-25) 4(-109.5,-75)
  rect 48x24 smd mask+2.99: 5(109.5,-75) 8(109.5,75)
  rect 48x24 smd paste-12 mask+2.99: 6(109.5,-25) 7(109.5,25)
  rect 150x154 smd paste-75 mask+2.99: 9(22.5,0)
  silkscreen extent -130,-104 59,104, body extent -121,-102 121,102, height 43
PWC0018A-MFG [mm] "Recommended Land Pattern"
  rrect22% 1.5x0.45 smd paste+0 mask+0: 1(-2.9,3.575) 2(-2.9,2.275) 3(-2.9,1.625) 4(-2.9,0.975) 5(-2.9,0.325) 6(-2.9,-0.325) 7(-2.9,-1.625) 8(-2.9,-2.275) 9(-2.9,-3.575) 10(2.9,-3.575) 11(2.9,-2.275) 12(2.9,-1.625) 13(2.9,-0.325) 14(2.9,0.325) 15(2.9,0.975) 16(2.9,1.625) 17(2.9,2.275) 18(2.9,3.575)
  rrect3% 3.4x7.8 smd paste-1000 mask-1000: 19(0,0)
  silkscreen extent -3.02,-4.28 2.25,4.47, body extent -3.75,-4.2 3.75,4.2, height 0.25
PWP0014C-MFG [mm]
  rrect33% 1.6x0.3 smd paste-1000 mask+0: 1(-2.8,1.95) 2(-2.8,1.3) 3(-2.8,0.65) 4(-2.8,0) 5(-2.8,-0.65) 6(-2.8,-1.3) 7(-2.8,-1.95) 8(2.8,-1.95) 9(2.8,-1.3) 10(2.8,-0.65) 11(2.8,0) 12(2.8,0.65) 13(2.8,1.3) 14(2.8,1.95)
  rrect3% 3.4x5 smd paste-1000 mask-1000: 15(0,0)
  silkscreen extent -3.12,-2.7 2.4,2.7, body extent -3.7,-2.8 3.7,2.8, height 0.25
PWP0016P-MFG [mm]
  rrect22% 1.5x0.45 smd paste+0 mask+0: 1(-2.9,2.275) 2(-2.9,1.625) 3(-2.9,0.975) 4(-2.9,0.325) 5(-2.9,-0.325) 6(-2.9,-0.975) 7(-2.9,-1.625) 8(-2.9,-2.275) 9(2.9,-2.275) 10(2.9,-1.625) 11(2.9,-0.975) 12(2.9,-0.325) 13(2.9,0.325) 14(2.9,0.975) 15(2.9,1.625) 16(2.9,2.275)
  rrect3% 3.4x5 smd paste-1000 mask-1000: 17(0,0)
  silkscreen extent -4.35,-2.95 2.25,2.95, body extent -3.75,-2.8 3.75,2.8, height 0.25
RGE0023A-MFG#1 [mm]
  rrect40% 0.6x0.25 smd paste+0 mask+0: 1(-1.9,1.25) 2(-1.9,0.75) 3(-1.9,0.25) 4(-1.9,-0.25) 5(-1.9,-0.75) 6(-1.9,-1.25) 13(1.9,-1.25) 14(1.9,-0.75) 15(1.9,-0.25) 16(1.9,0.25) 18(1.9,1.25)
  rrect40% 0.25x0.6 smd paste+0 mask+0: 7(-1.25,-1.9) 8(-0.75,-1.9) 9(-0.25,-1.9) 10(0.25,-1.9) 11(0.75,-1.9) 12(1.25,-1.9) 19(1.25,1.9) 20(0.75,1.9) 21(0.25,1.9) 22(-0.25,1.9) 23(-0.75,1.9) 24(-1.25,1.9)
  rrect5% 1.9x1.9 smd paste-1000 mask+0: 25(0,0)
  silkscreen extent -2.87,-2.05 2.05,2.05, body extent -2.3,-2.3 2.3,2.3, height 0.25
RGE0023A-MFG#2 [mm] "Recommended Land Pattern"
  rrect40% 0.6x0.25 smd paste+0 mask+0: 1(-1.9,1.25) 3(-1.9,0.25) 4(-1.9,-0.25) 5(-1.9,-0.75) 6(-1.9,-1.25) 13(1.9,-1.25) 14(1.9,-0.75) 15(1.9,-0.25) 16(1.9,0.25) 18(1.9,1.25)
  rrect37% 0.6x0.27 smd paste+0 mask+0: 2(-1.9,0.75)
  rrect40% 0.25x0.6 smd paste+0 mask+0: 7(-1.25,-1.9) 8(-0.75,-1.9) 9(-0.25,-1.9) 10(0.25,-1.9) 11(0.75,-1.9) 12(1.25,-1.9) 19(1.25,1.9) 20(0.75,1.9) 21(0.25,1.9) 22(-0.25,1.9) 23(-0.75,1.9) 24(-1.25,1.9)
  rrect5% 1.9x1.9 smd paste-1000 mask+0: 25(0,0)
  silkscreen extent -2.87,-2.05 2.05,2.05, body extent -2.3,-2.3 2.3,2.3, height 0.25
RGE0024T-MFG [mm]
  rrect40% 0.6x0.25 smd paste+0 mask+0: 1(-1.9,1.25) 2(-1.9,0.75) 3(-1.9,0.25) 4(-1.9,-0.25) 5(-1.9,-0.75) 6(-1.9,-1.25) 13(1.9,-1.25) 14(1.9,-0.75) 15(1.9,-0.25) 16(1.9,0.25) 17(1.9,0.75) 18(1.9,1.25)
  rrect40% 0.25x0.6 smd paste+0 mask+0: 7(-1.25,-1.9) 8(-0.75,-1.9) 9(-0.25,-1.9) 10(0.25,-1.9) 11(0.75,-1.9) 12(1.25,-1.9) 19(1.25,1.9) 20(0.75,1.9) 21(0.25,1.9) 22(-0.25,1.9) 23(-0.75,1.9) 24(-1.25,1.9)
  rrect5% 2.1x2.1 smd paste-1000 mask+0: 25(0,0)
  silkscreen extent -2.9,-2.05 2.05,2.05, body extent -2.3,-2.3 2.3,2.3, height 0.25
RGZ0048L-MFG [mm]
  rrect42% 0.6x0.24 smd paste+0 mask+0: 1(-3.4,2.75) 2(-3.4,2.25) 3(-3.4,1.75) 4(-3.4,1.25) 5(-3.4,0.75) 6(-3.4,0.25) 7(-3.4,-0.25) 8(-3.4,-0.75) 9(-3.4,-1.25) 10(-3.4,-1.75) 11(-3.4,-2.25) 12(-3.4,-2.75) 25(3.4,-2.75) 26(3.4,-2.25) 27(3.4,-1.75) 28(3.4,-1.25) 29(3.4,-0.75) 30(3.4,-0.25) 31(3.4,0.25) 32(3.4,0.75) 33(3.4,1.25) 34(3.4,1.75) 35(3.4,2.25) 36(3.4,2.75)
  rrect42% 0.24x0.6 smd paste+0 mask+0: 13(-2.75,-3.4) 14(-2.25,-3.4) 15(-1.75,-3.4) 16(-1.25,-3.4) 17(-0.75,-3.4) 18(-0.25,-3.4) 19(0.25,-3.4) 20(0.75,-3.4) 21(1.25,-3.4) 22(1.75,-3.4) 23(2.25,-3.4) 24(2.75,-3.4) 37(2.75,3.4) 38(2.25,3.4) 39(1.75,3.4) 40(1.25,3.4) 41(0.75,3.4) 42(0.25,3.4) 43(-0.25,3.4) 44(-0.75,3.4) 45(-1.25,3.4) 46(-1.75,3.4) 47(-2.25,3.4) 48(-2.75,3.4)
  rrect2% 4.6x4.975 smd paste-1000 mask+0: 49(0,-0.188)
  silkscreen extent -4.4,-3.55 3.55,3.55, body extent -3.8,-3.8 3.8,3.8, height 0.25
RXZ0016A-MFG [mm]
  rrect40% 0.65x0.25 smd paste+0 mask+0: 1(-1.625,2.375) 2(-1.625,1.875) 3(-1.625,1.375) 10(1.625,1.375) 11(1.625,1.875) 12(1.625,2.375)
  rrect40% 4x0.5 smd paste-1000 mask-1000: 4(0,0.7)
  rrect40% 1.925x0.5 smd paste-1000 mask-1000: 5(-1.037,-0.2) 6(-1.037,-1) 8(1.037,-1) 9(1.037,-0.2)
  rrect15% 4x1.35 smd paste-1000 mask-1000: 7(0,-2.325)
  rrect40% 0.25x0.65 smd paste+0 mask+0: 13(0.75,2.625) 14(0.25,2.625) 15(-0.25,2.625) 16(-0.75,2.625)
  silkscreen extent -2.62,-3.32 1.8,3.32, body extent -2.1,-3.1 2.1,3.05, height 0.25
RYT0009A-MFG [mm]
  rrect40% 0.875x0.25 smd paste+0 mask+0: 1(-0.763,0.25) 2(-0.763,-0.25) 5(0.763,-0.25) 6(0.763,0.25)
  round 0.255 smd paste+0 mask+0: 3(-0.509,-0.828)
  round 0.278 smd paste+0 mask+0: 4(0.487,-0.787)
  round 0.26 smd paste+0 mask+0: 7(0.537,0.787)
  rrect40% 0.25x0.65 smd paste+0 mask+0: 8(0,0.95)
  round 0.242 smd paste+0 mask+0: 9(-0.509,0.828)
  Top Shielding/Sig region: 1.2,-0.825 1.193,-0.85 1.175,-0.868 1.15,-0.875 1.15,-0.875 0.675,-0.875 0.656,-0.879 0.64,-0.89 0.629,-0.906 0.625,-0.925 0.625,-0.925 0.625,-1.225 0.618,-1.25 0.6,-1.268 0.575,-1.275 0.575,-1.275 0.425,-1.275 0.406,-1.271 0.39,-1.26 0.379,-1.244 0.375,-1.225 0.375,-1.225 0.375,-0.912 0.372,-0.894 0.363,-0.879 0.35,-0.868 0.35,-0.868 0.337,-0.857 0.328,-0.842 0.325,-0.825 0.325,-0.825 0.325,-0.675 0.329,-0.656 0.34,-0.64 0.356,-0.629 0.375,-0.625 0.375,-0.625 1.15,-0.625 1.169,-0.629 1.185,-0.64 1.196,-0.656 1.2,-0.675 1.2,-0.675
  Top Shielding/Sig region: -1.2,-0.825 -1.193,-0.85 -1.175,-0.868 -1.15,-0.875 -1.15,-0.875 -0.675,-0.875 -0.656,-0.879 -0.64,-0.89 -0.629,-0.906 -0.625,-0.925 -0.625,-0.925 -0.625,-1.225 -0.618,-1.25 -0.6,-1.268 -0.575,-1.275 -0.575,-1.275 -0.425,-1.275 -0.406,-1.271 -0.39,-1.26 -0.379,-1.244 -0.375,-1.225 -0.375,-1.225 -0.375,-0.912 -0.368,-0.887 -0.35,-0.868 -0.35,-0.868 -0.337,-0.857 -0.328,-0.842 -0.325,-0.825 -0.325,-0.825 -0.325,-0.675 -0.329,-0.656 -0.34,-0.64 -0.356,-0.629 -0.375,-0.625 -0.375,-0.625 -1.15,-0.625 -1.169,-0.629 -1.185,-0.64 -1.196,-0.656 -1.2,-0.675 -1.2,-0.675
  Top Shielding/Sig region: -1.2,0.825 -1.193,0.85 -1.175,0.868 -1.15,0.875 -1.15,0.875 -0.675,0.875 -0.656,0.879 -0.64,0.89 -0.629,0.906 -0.625,0.925 -0.625,0.925 -0.625,1.225 -0.618,1.25 -0.6,1.268 -0.575,1.275 -0.575,1.275 -0.425,1.275 -0.406,1.271 -0.39,1.26 -0.379,1.244 -0.375,1.225 -0.375,1.225 -0.375,0.675 -0.379,0.656 -0.39,0.64 -0.406,0.629 -0.425,0.625 -0.425,0.625 -1.15,0.625 -1.169,0.629 -1.185,0.64 -1.196,0.656 -1.2,0.675 -1.2,0.675
  Top Shielding/Sig region: 1.2,0.825 1.193,0.85 1.175,0.868 1.15,0.875 1.15,0.875 0.675,0.875 0.656,0.879 0.64,0.89 0.629,0.906 0.625,0.925 0.625,0.925 0.625,1.225 0.618,1.25 0.6,1.268 0.575,1.275 0.575,1.275 0.425,1.275 0.406,1.271 0.39,1.26 0.379,1.244 0.375,1.225 0.375,1.225 0.375,0.675 0.379,0.656 0.39,0.64 0.406,0.629 0.425,0.625 0.425,0.625 1.15,0.625 1.169,0.629 1.185,0.64 1.196,0.656 1.2,0.675 1.2,0.675
  silkscreen extent -1.92,-1.68 1.05,1.68, body extent -1.3,-1.38 1.3,1.38, height 0.25
RZT0020A-MFG [mm]
  round 0.259 smd paste+0 mask+0: 1(-1.069,1.519) 7(-1.069,-1.569) 11(1.069,-1.569) 17(1.069,1.519)
  rrect40% 0.6x0.25 smd paste+0 mask+0: 2(-1.2,1) 3(-1.2,0.5) 4(-1.2,0) 5(-1.2,-0.5) 6(-1.2,-1) 12(1.2,-1) 13(1.2,-0.5) 14(1.2,0) 15(1.2,0.5) 16(1.2,1)
  rrect40% 0.25x0.6 smd paste+0 mask+0: 8(-0.55,-1.7) 9(-0.05,-1.7) 10(0.5,-1.7) 18(0.5,1.7) 19(-0.05,1.7) 20(-0.55,1.7)
  round 0.855 smd paste-1000 mask+0: 21(-0.075,0)
  Top Shielding/Sig region: 1.45,-1.375 1.469,-1.379 1.485,-1.39 1.496,-1.406 1.5,-1.425 1.5,-1.425 1.5,-1.575 1.496,-1.594 1.485,-1.61 1.469,-1.621 1.45,-1.625 1.45,-1.625 1.275,-1.625 1.237,-1.633 1.204,-1.654 1.183,-1.687 1.175,-1.725 1.175,-1.725 1.175,-1.95 1.171,-1.969 1.16,-1.985 1.144,-1.996 1.125,-2 1.125,-2 0.975,-2 0.956,-1.996 0.94,-1.985 0.929,-1.969 0.925,-1.95 0.925,-1.95 0.925,-1.425 0.929,-1.406 0.94,-1.39 0.956,-1.379 0.975,-1.375 0.975,-1.375
  Top Shielding/Sig region: 1.45,1.375 1.469,1.379 1.485,1.39 1.496,1.406 1.5,1.425 1.5,1.425 1.5,1.575 1.496,1.594 1.485,1.61 1.469,1.621 1.45,1.625 1.45,1.625 1.275,1.625 1.237,1.633 1.204,1.654 1.183,1.687 1.175,1.725 1.175,1.725 1.175,1.95 1.171,1.969 1.16,1.985 1.144,1.996 1.125,2 1.125,2 0.975,2 0.956,1.996 0.94,1.985 0.929,1.969 0.925,1.95 0.925,1.95 0.925,1.425 0.929,1.406 0.94,1.39 0.956,1.379 0.975,1.375 0.975,1.375
  Top Shielding/Sig region: -0.55,1 -0.543,1.025 -0.525,1.043 -0.5,1.05 -0.5,1.05 0.099,1.05 0.124,1.044 0.142,1.026 0.149,1.001 0.149,1.001 0.178,0.897 0.252,0.819 0.354,0.785 0.354,0.785 0.377,0.777 0.394,0.759 0.4,0.735 0.4,0.735 0.4,-0.735 0.394,-0.759 0.377,-0.777 0.354,-0.785 0.354,-0.785 0.252,-0.819 0.178,-0.897 0.149,-1.001 0.149,-1.001 0.142,-1.026 0.124,-1.044 0.099,-1.05 0.099,-1.05 -0.249,-1.05 -0.274,-1.044 -0.292,-1.026 -0.299,-1.001 -0.299,-1.001 -0.328,-0.897 -0.402,-0.819 -0.504,-0.785 -0.504,-0.785 -0.527,-0.777 -0.544,-0.759 -0.55,-0.735 -0.55,-0.735
  Top Shielding/Sig region: -1.45,1.375 -1.469,1.379 -1.485,1.39 -1.496,1.406 -1.5,1.425 -1.5,1.425 -1.5,1.575 -1.493,1.6 -1.475,1.618 -1.45,1.625 -1.45,1.625 -1.275,1.625 -1.237,1.633 -1.204,1.654 -1.183,1.687 -1.175,1.725 -1.175,1.725 -1.175,1.95 -1.168,1.975 -1.15,1.993 -1.125,2 -1.125,2 -0.975,2 -0.956,1.996 -0.94,1.985 -0.929,1.969 -0.925,1.95 -0.925,1.95 -0.925,1.425 -0.929,1.406 -0.94,1.39 -0.956,1.379 -0.975,1.375 -0.975,1.375
  Top Shielding/Sig region: -1.45,-1.375 -1.469,-1.379 -1.485,-1.39 -1.496,-1.406 -1.5,-1.425 -1.5,-1.425 -1.5,-1.575 -1.496,-1.594 -1.485,-1.61 -1.469,-1.621 -1.45,-1.625 -1.45,-1.625 -1.275,-1.625 -1.237,-1.633 -1.204,-1.654 -1.183,-1.687 -1.175,-1.725 -1.175,-1.725 -1.175,-1.95 -1.171,-1.969 -1.16,-1.985 -1.144,-1.996 -1.125,-2 -1.125,-2 -0.975,-2 -0.956,-1.996 -0.94,-1.985 -0.929,-1.969 -0.925,-1.95 -0.925,-1.95 -0.925,-1.425 -0.929,-1.406 -0.94,-1.39 -0.956,-1.379 -0.975,-1.375 -0.975,-1.375
  silkscreen extent -2.17,-2.22 1.73,2.22, body extent -1.6,-2.1 1.6,2.1, height 0.25
SM_RADIAL_E [mm] "8 x 6.2mm:  Panasonic E"
  rect 4x1.6 smd: 1(-3.1,0) 2(3.1,0)
  silkscreen extent -4.25,-4.25 4.25,4.25, body extent -4.25,-4.25 4.25,4.25, height 6.5
SM_RADIAL_H13 [mm] "12.5 x 13.5mm:  Panasonic H13"
  rect 5.7x2 smd: 1(-4.85,0) 2(4.85,0)
  silkscreen extent -6.85,-6.85 6.85,6.85, body extent -6.85,-6.85 6.85,6.85, height 14
SMA [mm] "Molded Diode, 2-Leads, Body 4.3x2.6mm, IPC Medium Density, based on OnSemi component dimensions and land pattern"
  rect 2x2 smd: 1(-2,0) 2(2,0)
  silkscreen extent -3.66,-1.57 2.79,1.57, body extent -2.6,-1.3 2.6,1.3, height 2.42
SMA_Bi [mm] "SMD, 2-Leads, Body 4.275x2.575mm"
  rect 1.4x1.64 smd: 1(-2.015,0) 2(2.015,0)
  silkscreen extent -2.3,-1.45 2.3,1.45, body extent -2.52,-1.45 2.52,1.45, height 2.65
SMB [mm] "Molded Diode, 2-Leads, Body 5.4x3.6mm, IPC Medium Density, based on OnSemi component dimensions"
  rect 2.159x2.743 smd: 1(-2.21,0) 2(2.21,0)
  silkscreen extent -3.94,-2.08 3.18,2.08, body extent -2.7,-1.8 2.7,1.8, height 2.32
SMC [mil] "Molded Diode, 2-Leads, Body 6.9x5.8mm, IPC Medium Density, based on OnSemi component dimensions and land patterns"
  rect 110x150 smd: 1(-140.49,0) 2(140.49,0)
  silkscreen extent -221,-124 189,123, body extent -156,-116 156,116, height 91
SNT-100-BK-G [mil] "Samtec STEP model"
  round 1 on Mech3: 0(0,0)
  body extent -100,-50 100,50, height 344
SOD-123 [mm] "On Semi recommended land pattern"
  rect 0.915x1.22 smd: 1(-1.637,0) 2(1.637,0)
  silkscreen extent -2.74,-1.17 2.03,1.17, body extent -1.93,-0.9 1.93,0.9, height 1.35
SOT-323 [mm] "Diodes Inc recommended land pattern.  2016-02-24"
  rrect21% 0.6x0.47 smd: 1(-0.95,0.65) 2(-0.95,-0.65) 3(0.95,0)
  silkscreen extent -1.14,-1.22 0.77,1.22, body extent -1.13,-1.13 1.12,1.12, height 1.13
SOT-416 [mm] "NXP recommended footprint."
  rect 0.6x0.5 smd: 1(-0.65,0.5) 2(-0.65,-0.5) 3(0.65,0)
  silkscreen extent -0.13,-0.9 0.5,0.9, body extent -0.8,-0.9 0.8,0.9, height 0.82
SW_147873-2 [mm] "SMD, 2-Leads, Body 6x3.5mm"
  rect 2.8x2.2 smd: 1(-2.4,0) 2(2.4,0)
  silkscreen extent -2.93,-1.75 2.93,1.75, body extent -3.4,-1.75 3.4,1.75, height 4.5
TI_Stacked_Overlay_Small [mm]
  silkscreen extent -10.63,-2.49 10.63,2.49
TNPW0603 [mm] "Vishay"
  rect 0.5x0.9 smd: 1(-0.75,0) 2(0.75,0)
  silkscreen extent -0.2,-0.6 0.2,0.6, body extent -0.85,-0.47 0.85,0.47, height 0.55
TSW-103-07-G-S [mm] "Samtec 100mil, 1x3, 230 mil above insulator"
  rrect50% 1.65x1.65 hole 1.016: 1(-2.54,0)
  round 1.65 hole 1.016: 2(0,0) 3(2.54,0)
  body extent -3.81,-1.27 3.81,1.27, height 8.38
TSW-104-07-G-S [mm] "Samtec 100mil, 1x4, 230 mil above insulator"
  rrect50% 1.65x1.65 hole 1.016: 1(-3.81,0)
  round 1.65 hole 1.016: 2(-1.27,0) 3(1.27,0) 4(3.81,0)
  body extent -5.08,-1.27 5.08,1.27, height 8.38
VAK0015A-MFG [mm]
  rrect40% 0.65x0.25 smd paste+0 mask+0: 1(-1.625,2.375) 2(-1.625,1.875) 3(-1.625,1.375) 8(1.625,1.375) 9(1.625,1.875) 10(1.625,2.375)
  rrect17% 4x0.6 smd paste-1000 mask-1000: 4(0,0.4)
  rrect20% 1.75x1 smd paste-1000 mask-1000: 5(-1.125,-0.9) 7(1.125,-0.9)
  rrect15% 4x1.35 smd paste-1000 mask-1000: 6(0,-2.575)
  rrect40% 0.25x0.65 smd paste+0 mask+0: 11(1,2.875) 12(0.5,2.875) 13(0,2.875) 14(-0.5,2.875) 15(-1,2.875)
  silkscreen extent -2.62,2.25 1.8,3.05, body extent -2.1,-3.35 2.1,3.3, height 0.25
WCAP-ATUL_D10H20 [mm] "Aluminum Electrolytic Capacitors, 10x20mm"
  rrect50% 1.4x1.4 hole 0.9: 1(2.5,0)
  round 1.4 hole 0.9: 2(-2.5,0)
  silkscreen extent -5.25,-5.25 5.25,5.25, body extent -4.99,-5 5,5, height 20.31
WCAP-CSGP_0402_L1W0.5H0.5 [mm] "Ceramic Capacitors, body 1x0.5mm"
  rect 0.5x0.5 smd: 1(-0.5,0) 2(0.5,0)
  body extent -0.5,-0.25 0.5,0.25, height 0.5
WE-HCC_1210 [mm] "WURTH"
  rect 2.9x5.4 smd: 1(-4.95,0) 2(4.95,0)
  silkscreen extent -6,-5.9 6,5.9, body extent -6,-5.85 6,5.85, height 10
WE-PD_1210 [mm] "Wurth Elektronik recommended land pattern"
  rect 2.9x5.4 smd: 1(-4.95,0) 2(4.95,0)
  silkscreen extent -6,-6 6,6, body extent -6,-6 6,6, height 10.01
WE-TPC-XLH2 [mm] "Wurth Elektronik recommended land pattern, 2008-04-11"
  rect 1.8x4.6 smd: 1(-4.5,0) 2(4.5,0)
  silkscreen extent -5.15,-5.15 5.15,5.15, body extent -5.15,-5.15 5.15,5.15, height 3.1
WEEE_Minimum [mm] "WEEElie bin"
  silkscreen extent -2.42,-4.38 2.52,2.65
WL-SMCW_RED [mm] "WURTH"
  rect 0.8x0.8 smd: 1(-0.8,0) 2(0.8,0)
  silkscreen extent -1.9,-0.8 1.2,0.8, body extent -0.85,-0.45 0.85,0.45, height 0.8

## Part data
C1: library part CMP-0094833-1, "10 µF 50 V Aluminum Electrolytic Capacitors Radial, Can - SMD - 1000 Hrs @ 105°C", Digikey Part Number=PCE4209CT-ND, Leakage Current=5uA, Manufacturer="Panasonic Electronic Components", Mouser Part Number=667-EEE-HA1H100P, Operating Temperature Range="-40°C to +105°C", Tolerance_%=20%, ValueDisplayed=10uF
C2 C8 C17: library part CMP-0094511-1, "0.1 µF ±5% 50V Ceramic Capacitor X7R 0603 (1608 Metric)", Digikey Part Number=478-7426-1-ND, Manufacturer="KYOCERA AVX", Mouser Part Number=581-06035C104J4Z2A, Operating Temperature Range=to, TempCo=15%, Temperature Characteristic=X7R, Tolerance_%=5%, ValueDisplayed=0.1uF
C3 C4 C5 C26: library part CMP-0006837-2, "CAP, CERM, 0.1 uF, 50 V, +/- 10%, X7R, 0603", Cap_Case=0603, Manufacturer="Wurth Elektronik", TempCo=X7R, Tolerance_%=10%, Value1=Unknown, Value2=50V, ValueDisplayed=0.1uF
C6 C25: library part CMP-0122528-1, "Cap Ceramic 0.1uF 50V X7R 5% SMD 1.6 x 0.8 mm 125 C Paper T/R", Digikey Part Number=399-C0603C104J5RAC7867CT-ND, Manufacturer=KEMET, Mouser Part Number=80-C0603C104J5R, Operating Temperature Range="-55°C to +125°C", TempCo=15%, Temperature Characteristic=X7R, Tolerance_%=5%, ValueDisplayed=0.1uF
C7 C18 C126 C156: library part CMP-0122257-1, "1 µF ±10% 50V Ceramic Capacitor X7R 0603 (1608 Metric)", Digikey Part Number=1276-CL10B105KB9VPJCCT-ND, Manufacturer=Samsung, Mouser Part Number=187-CL10B105KB9VPJC, Operating Temperature Range="-55°C to +125°C", TempCo=15%, Temperature Characteristic=X7R, Tolerance_%=10%, ValueDisplayed=1uF
C9 C16: library part CMP-0095668-2, "Ceramic Capacitor 10nF ±10% 50V X7R 0603", Manufacturer=Murata, Operating Temperature Range="-55°C to +125°C", TempCo=15%, Temperature Characteristic=X7R, Tolerance_%=10%, ValueDisplayed=10nF
C10 C15 C190 C191 C192 C193 C194 C195 C196 C197 C198: library part CMP-0094874-1, "Cap Ceramic 1nF 50V X7R 10% Pad SMD 0603 +125°C Automotive T/R", Manufacturer=TDK, Operating Temperature Range="-55°C to +125°C", TempCo=0.15, Temperature Characteristic=X7R, Tolerance_%=0.1%, ValueDisplayed=1nF
C11 C12 C13 C14 C28 C29 C30 C31: library part CMP-0102582-1, "WCAP-ATUL Aluminum Electrolytic Capacitor, Radial, THT, D10 x H20mm, 82µF, 100V", Capacitance Tolerance=20%, Leakage Current=82uA, Manufacturer="Wurth Elektronik", Operating Temperature Max=105°C, Operating Temperature Min=-40°C, Rated Voltage (DC)=100V, Ripple Current=600mA
C19 C106: library part CMP-0011164-2, "CAP, AL, 10 uF, 100 V, +/- 20%, AEC-Q200 Grade 3, SMD", Cap_Case=8.0x6.0mm, Manufacturer=Panasonic, Supplier Part Number 1=PCE3966CT-ND, Tolerance_%=20%, Value1=Unknown, Value2=100V, ValueDisplayed=10uF
C20 C22: library part CMP-0008709-2, "CAP, CERM, 0.1 uF, 100 V, +/- 10%, X7R, 1206", Cap_Case=1206_180, Manufacturer=TDK, Supplier Part Number 1=445-1377-1-ND, TempCo=X7R, Tolerance_%=10%, Value1="0.030343 ohm", Value2=100V, ValueDisplayed=0.1uF
C21 C24 C79 C85 C113 C121 C143 C149: library part CMP-0007081-4, "CAP, CERM, 1000 pF, 100 V, +/- 10%, X7R, AEC-Q200 Grade 1, 0603", Cap_Case=0603, Manufacturer=TDK, Supplier Part Number 1=445-5806-1-ND, TempCo=X7R, Tolerance_%=10%, Value1="1.97137 ohm", Value2=100V, ValueDisplayed=1000pF
C23 C105: library part CMP-0115207-1, "WCAP-CSGP Multilayer Ceramic Chip Capacitor, General Purpose, size 0402, X5R, 100nF, 6.3VDC", Capacitance Tolerance=+/-20%, Insulation Resistance=1GOhm, Manufacturer="Wurth Elektronik", Operating Temperature Max=85°C, Operating Temperature Min=-55°C, Rated Voltage (DC)=6.3V
C27 C33: library part CMP-0097294-1, "0.1 µF ±10% 100V Ceramic Capacitor X7R 0603 (1608 Metric)", Digikey Part Number=732-885012206120TR-ND, Manufacturer="Wurth Electronics", Mouser Part Number=710-885012206120, Operating Temperature Range="-55°C to +125°C", TempCo=15%, Temperature Characteristic=X7R, Tolerance_%=10%, ValueDisplayed=100nF
C32 C38: library part CMP-0007891-2, "CAP, CERM, 1 uF, 100 V, +/- 10%, X7S, 0805", Cap_Case=0805, Manufacturer=TDK, Supplier Part Number 1=445-5205-1-ND, TempCo=X7S, Tolerance_%=10%, Value1="0.008255 ohm", Value2=100V, ValueDisplayed=1uF
C34 C37: library part CMP-0079993-1, "CAP, CERM, 0.01 µF, 100 V,+/- 10%, X7R, 0603", Cap_Case=0603, Manufacturer="Wurth Elektronik", Supplier Part Number 1=45AC8565, TempCo=X7R, Tolerance_%=10%, Value2=100V, ValueDisplayed=0.01µF
C35 C36: library part CMP-0006724-5, "CAP, CERM, 1000 pF, 100 V, +/- 10%, X7R, 0603", Cap_Case=0603, Manufacturer=AVX, Supplier Part Number 1=478-1199-1-ND, TempCo=X7R, Tolerance_%=10%, Value1="0.276 ohm", Value2=100V, ValueDisplayed=1000pF
C39 C48 C50 C74 C76 C83: library part CMP-0006976-5, "CAP, CERM, 1000 pF, 50 V, +/- 10%, X7R, 0603", Cap_Case=0603, Manufacturer=Kemet, Supplier Part Number 1=399-5348-1-ND, TempCo=X7R, Tolerance_%=10%, Value1=Unknown, Value2=50V, ValueDisplayed=1000pF
C40: library part CMP-0007085-4, "CAP, CERM, 2200 pF, 100 V, +/- 10%, X7R, AEC-Q200 Grade 1, 0603", Cap_Case=0603, Manufacturer=TDK, Supplier Part Number 1=445-5808-1-ND, TempCo=X7R, Tolerance_%=10%, Value1="0.923948 ohm", Value2=100V, ValueDisplayed=2200pF
C41 C42 C43 C47 C115 C117 C145 C148: library part CMP-0009477-2, "CAP, CERM, 15 uF, 100 V, +/- 20%, X7R, Stacked 2220", Cap_Case=2220, Manufacturer=MuRata, Supplier Part Number 1=490-5838-1-ND, TempCo=X7R, Tolerance_%=20%, Value1=Unknown, Value2=100V, ValueDisplayed=15uF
